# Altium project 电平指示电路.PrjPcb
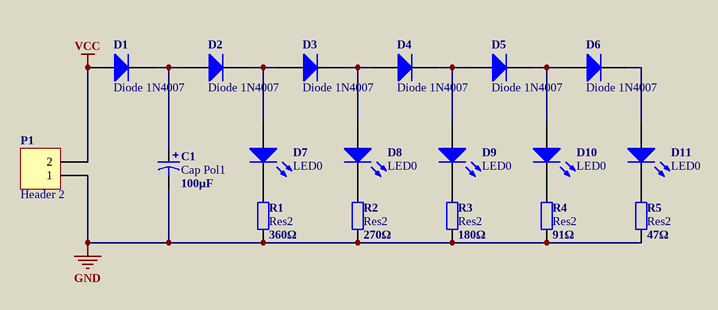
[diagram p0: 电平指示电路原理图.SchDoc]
1 sheet, 18 parts. Net scope: global (net labels, ports and power ports of the same name join across sheets).
Board file: 电平指示电路PCB.PcbDoc

## Sheet 电平指示电路原理图.SchDoc
size A4

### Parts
C1  Cap Pol1  value 100μF  [RB7.6-15]
D1  Diode 1N4007  [DO-41]
D2  Diode 1N4007  [DO-41]
D3  Diode 1N4007  [DO-41]
D4  Diode 1N4007  [DO-41]
D5  Diode 1N4007  [DO-41]
D6  Diode 1N4007  [DO-41]
D7  LED0  [LED-0]
D8  LED0  [LED-0]
D9  LED0  [LED-0]
D10  LED0  [LED-0]
D11  LED0  [LED-0]
P1  Header 2  [HDR1X2]
R1  Res2  value 360Ω  [AXIAL-0.4]
R2  Res2  value 270Ω  [AXIAL-0.4]
R3  Res2  value 180Ω  [AXIAL-0.4]
R4  Res2  value 91Ω  [AXIAL-0.4]
R5  Res2  value 47Ω  [AXIAL-0.4]

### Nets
GND: C1.2 P1.1 R1.1 R2.2 R3.2 R4.2 R5.2
VCC: D1.1(A) P1.2
NetC1_1: C1.1 D1.2(K) D2.1(A)
NetD2_2: D2.2(K) D3.1(A) D7.1(A)
NetD3_2: D3.2(K) D4.1(A) D8.1(A)
NetD4_2: D4.2(K) D5.1(A) D9.1(A)
NetD5_2: D5.2(K) D6.1(A) D10.1(A)
NetD6_2: D6.2(K) D11.1(A)
NetD7_2: D7.2(K) R1.2
NetD8_2: D8.2(K) R2.1
NetD9_2: D9.2(K) R3.1
NetD10_2: D10.2(K) R4.1
NetD11_2: D11.2(K) R5.1

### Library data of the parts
C1 = Cap Pol1: Polarized Capacitor (Radial)
D1-D6 = Diode 1N4007: 1 Amp General Purpose Rectifier
D7-D11 = LED0: Typical INFRARED GaAs LED
P1 = Header 2: Header, 2-Pin
R1-R5 = Res2: Resistor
